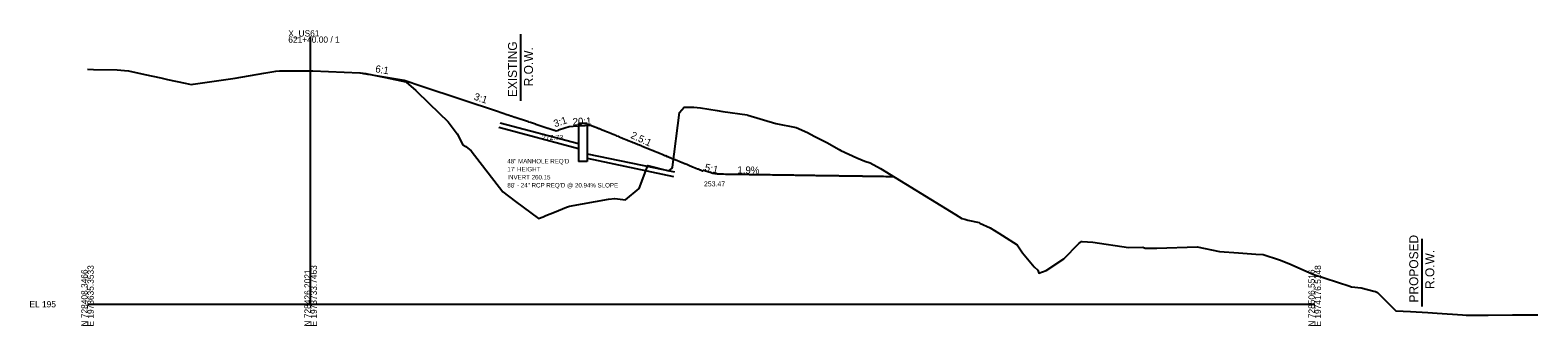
# Model space of a CAD drawing. Extents: x -26 to 1629, y -25 to 9635.
# Drawn here: x -26 to 650, y 3490 to 3623 of the extents above; entities that cross this region are included whole.
import ezdxf

# ---------------------------------------------------------------- set-up
doc = ezdxf.new("R2010")
doc.units = 0
for name, color, linetype in [('Default', 7, 'Continuous'), ('Draft_XS_Grid', 7, 'Continuous'), ('DTM CONTOURS_MAJOR', 7, 'Continuous'), ('DTM_X_GROUND', 7, 'Continuous'), ('XS_CELL', 7, 'Continuous'), ('XS_P_DRAINAGE', 7, 'Continuous'), ('XS_P_GROUND', 7, 'Continuous'), ('XS_P_ROW', 7, 'Continuous'), ('XS_P_TX_DCH', 7, 'Continuous'), ('XS_P_TX_FS_BS', 7, 'Continuous'), ('XS_X_ROW', 7, 'Continuous')]:
    doc.layers.add(name, color=color, linetype=linetype)

msp = doc.modelspace()

# ---------------------------------------------------------------- linework, layer by layer
at = {"layer": 'DTM_X_GROUND'}
msp.add_lwpolyline([(0, 3605.28), (2.68, 3605.23), (13.32, 3605.03), (16.59, 3604.73), (18.31, 3604.58), (25.67, 3602.96), (32.85, 3601.46), (35.86, 3600.73), (43.76, 3599.08), (46.43, 3598.52), (47.39, 3598.66), (66.25, 3601.39), (78.98, 3603.51), (84.39, 3604.52), (86.08, 3604.59), (87.2, 3604.64), (93.1, 3604.62), (101.01, 3604.6), (115.06, 3604.01), (122.06, 3603.72), (123.13, 3603.62), (124.81, 3603.45), (126.15, 3603.17), (133.54, 3601.57), (142.62, 3599.63), (142.78, 3599.48), (147.09, 3595.84), (153.2, 3589.92), (161.62, 3581.77), (165.72, 3576.42), (168.27, 3571.44), (169.57, 3570.66), (171.92, 3568.79), (186.1, 3550.37), (191.86, 3546.06), (202.11, 3538.39), (204.16, 3539.19), (205.48, 3539.73), (209.36, 3541.27), (214.72, 3543.43), (215.96, 3543.93), (233.43, 3547.02), (236.34, 3547.42), (241.16, 3546.78), (247.21, 3551.8), (251.1, 3562.23), (260.54, 3559.82), (262.02, 3560.94), (262.24, 3561.41), (265.31, 3585.98), (267.34, 3588.35), (271.68, 3588.3), (274.68, 3587.98), (282.22, 3586.78), (284.74, 3586.38), (295.61, 3584.84), (295.77, 3584.82), (295.99, 3584.78), (308.5, 3580.93), (317.6, 3579.19), (322.68, 3577.01), (325.6, 3575.26), (331.3, 3572.49), (336.92, 3569.29), (337.61, 3568.94), (344.82, 3565.68), (348.37, 3564.07), (350.75, 3563.31), (355.47, 3560.78), (388.99, 3540.26), (391.82, 3538.45), (393.22, 3538.06), (394.6, 3537.69), (399.58, 3536.65), (399.97, 3536.35), (404.54, 3534.23), (408.39, 3531.87), (408.43, 3531.85), (416.68, 3526.57), (419.11, 3523.07), (424.28, 3516.78), (425.92, 3515.28), (426.39, 3513.96), (429.6, 3515.18), (437.51, 3520.41), (444.3, 3527.23), (445.55, 3528.18), (445.73, 3528.17), (450.6, 3527.76), (466.49, 3525.39), (472.94, 3525.51), (473.98, 3525.19), (479.17, 3525.18), (497.34, 3525.7), (507.4, 3523.58), (515.77, 3523.1), (523.59, 3522.42), (526.92, 3522.33), (534.2, 3519.84), (537.69, 3518.58), (539.41, 3517.77), (549.19, 3513.43), (565.69, 3508.07), (566.08, 3507.92), (566.44, 3507.85), (570.83, 3507.3), (576.56, 3505.89), (577.22, 3505.75), (578.15, 3505.22), (586.3, 3497.08), (593, 3496.69), (600.64, 3496.25), (604.93, 3496), (616.16, 3495.24), (617.91, 3495.15), (627.74, 3495.13), (638.58, 3495.24), (650, 3495.24)], dxfattribs=at)
at = {"layer": 'XS_CELL'}
for p, q in [((100, 3500), (100, 3620)), ((0, 3500), (100, 3500)), ((100, 3500), (550, 3500))]:
    msp.add_line(p, q, dxfattribs=at)
at = {"layer": 'XS_P_DRAINAGE'}
for p, q in [((184.88, 3581.32), (220, 3571.97)), ((184.36, 3579.39), (220.11, 3569.87)), ((220, 3581.01), (220, 3563.98)), ((224, 3581.01), (220, 3581.01)), ((224, 3581.01), (224, 3563.98)), ((224, 3563.98), (220, 3563.98)), ((224, 3567.45), (263.02, 3559.28)), ((224, 3565.4), (262.61, 3557.32))]:
    msp.add_line(p, q, dxfattribs=at)
at = {"layer": 'XS_P_GROUND'}
for points in [[(122, 3603.73), (122.36, 3603.67), (123.4, 3603.49), (123.92, 3603.41), (125.48, 3603.15), (127.03, 3602.89), (127.55, 3602.8), (142, 3600.39)], [(142, 3600.39), (149.91, 3597.76), (150.24, 3597.64), (184.18, 3586.33), (184.89, 3586.1), (184.9, 3586.09), (185.34, 3585.94), (185.39, 3585.93), (187.15, 3585.34), (187.34, 3585.28), (187.45, 3585.24), (188.95, 3584.74), (189.77, 3584.47), (189.86, 3584.44), (191.55, 3583.87), (191.67, 3583.83), (193.42, 3583.25), (193.49, 3583.23), (194.38, 3582.93), (194.4, 3582.92), (194.45, 3582.91), (196.23, 3582.32), (196.25, 3582.31), (197.14, 3582.01), (197.16, 3582.01), (197.69, 3581.83), (197.71, 3581.82), (198.55, 3581.54), (198.56, 3581.54), (198.98, 3581.4), (199, 3581.39), (199.89, 3581.09), (199.92, 3581.09), (200.81, 3580.79), (200.87, 3580.77), (203.12, 3580.02), (203.13, 3580.02), (203.58, 3579.87), (203.62, 3579.85), (204, 3579.73), (204.51, 3579.55), (206.3, 3578.96), (206.38, 3578.93), (206.43, 3578.92), (208.26, 3578.31), (208.28, 3578.3), (209.2, 3577.99), (209.24, 3577.98), (210, 3577.73), (210, 3577.73), (211.08, 3578.08), (211.15, 3578.11), (213.91, 3579.03), (213.96, 3579.04), (215.8, 3579.66), (215.83, 3579.67), (216, 3579.73), (216.02, 3579.73), (217.7, 3579.81), (217.72, 3579.81), (225.73, 3580.21)], [(225.72, 3580.21), (225.83, 3580.17), (225.84, 3580.17), (226.96, 3579.71), (227.04, 3579.67), (228.1, 3579.24), (228.24, 3579.19), (229.23, 3578.78), (229.43, 3578.7), (230.36, 3578.32), (230.62, 3578.21), (231.5, 3577.85), (231.81, 3577.73), (232.63, 3577.39), (232.99, 3577.24), (233.76, 3576.93), (234.49, 3576.63), (234.9, 3576.46), (235.62, 3576.17), (236.03, 3576), (236.74, 3575.71), (237.16, 3575.54), (237.86, 3575.25), (238.3, 3575.07), (238.98, 3574.79), (239.43, 3574.61), (240.1, 3574.33), (240.56, 3574.15), (241.22, 3573.88), (241.7, 3573.68), (242.34, 3573.42), (242.83, 3573.22), (243.46, 3572.96), (243.96, 3572.76), (244.58, 3572.51), (245.1, 3572.29), (245.69, 3572.05), (246.23, 3571.83), (246.81, 3571.59), (247.36, 3571.37), (247.92, 3571.14), (248.5, 3570.9), (249.04, 3570.68), (249.63, 3570.44), (250.15, 3570.23), (250.76, 3569.98), (251.26, 3569.77), (251.9, 3569.51), (252.37, 3569.32), (253.03, 3569.05), (253.48, 3568.87), (254.16, 3568.59), (254.58, 3568.41), (255.3, 3568.12), (255.69, 3567.96), (256.43, 3567.66), (256.79, 3567.51), (257.56, 3567.2), (257.89, 3567.06), (258.7, 3566.73), (258.98, 3566.61), (259.83, 3566.27), (260.08, 3566.17), (260.96, 3565.81), (261.17, 3565.72), (262.1, 3565.34), (262.25, 3565.28), (263.23, 3564.88), (263.33, 3564.84), (264.36, 3564.42), (264.41, 3564.4), (265.23, 3564.06), (265.47, 3563.96), (265.5, 3563.95), (266.5, 3563.54), (266.63, 3563.49), (267.52, 3563.13), (267.76, 3563.03), (268.54, 3562.71), (268.9, 3562.56), (269.57, 3562.29), (270.03, 3562.1), (270.59, 3561.87), (271.16, 3561.64), (271.62, 3561.45), (272.3, 3561.17), (272.64, 3561.03), (273.43, 3560.71), (273.66, 3560.61), (274.56, 3560.25), (274.69, 3560.19), (275.7, 3559.78), (275.71, 3559.78), (275.86, 3559.72)], [(282.23, 3558.47), (281.49, 3558.51), (281.36, 3558.51), (280.73, 3558.54), (280.54, 3558.55), (280.45, 3558.58), (280.23, 3558.65), (279.8, 3558.79), (279.1, 3559.02), (278.42, 3559.25), (277.96, 3559.4), (277.04, 3559.7), (276.83, 3559.77), (276.68, 3559.82), (275.86, 3560.09)], [(361.45, 3557.12), (361.35, 3557.12), (361.34, 3557.12), (360.19, 3557.14), (360.16, 3557.14), (359.03, 3557.15), (358.98, 3557.15), (357.87, 3557.17), (357.8, 3557.17), (356.72, 3557.19), (356.61, 3557.19), (355.56, 3557.2), (355.43, 3557.21), (354.4, 3557.22), (354.25, 3557.22), (353.24, 3557.24), (353.07, 3557.24), (352.09, 3557.25), (351.89, 3557.26), (350.93, 3557.27), (350.71, 3557.27), (349.77, 3557.29), (349.54, 3557.29), (348.61, 3557.3), (348.36, 3557.31), (347.46, 3557.32), (347.18, 3557.33), (346.3, 3557.34), (346, 3557.34), (345.14, 3557.35), (344.83, 3557.36), (343.98, 3557.37), (343.66, 3557.38), (342.83, 3557.39), (342.48, 3557.39), (341.67, 3557.4), (341.31, 3557.41), (340.51, 3557.42), (340.13, 3557.43), (339.35, 3557.44), (338.96, 3557.44), (338.19, 3557.46), (337.78, 3557.46), (337.04, 3557.47), (336.6, 3557.48), (335.88, 3557.49), (335.43, 3557.5), (334.72, 3557.51), (334.25, 3557.51), (333.56, 3557.52), (333.07, 3557.53), (332.41, 3557.54), (331.9, 3557.55), (331.25, 3557.56), (330.72, 3557.56), (330.09, 3557.57), (329.54, 3557.58), (328.93, 3557.59), (328.36, 3557.6), (327.78, 3557.61), (327.18, 3557.61), (326.62, 3557.62), (326, 3557.63), (325.46, 3557.64), (324.83, 3557.65), (324.3, 3557.66), (323.65, 3557.67), (323.15, 3557.67), (322.47, 3557.68), (321.99, 3557.69), (321.29, 3557.7), (320.83, 3557.71), (320.11, 3557.72), (319.67, 3557.72), (318.94, 3557.73), (318.52, 3557.74), (317.76, 3557.75), (317.36, 3557.76), (316.58, 3557.77), (316.2, 3557.77), (315.4, 3557.78), (315.04, 3557.79), (314.23, 3557.8), (313.89, 3557.81), (313.05, 3557.82), (312.73, 3557.82), (311.87, 3557.84), (311.57, 3557.84), (310.7, 3557.85), (310.41, 3557.86), (309.52, 3557.87), (309.25, 3557.87), (308.34, 3557.89), (308.1, 3557.89), (307.17, 3557.9), (306.94, 3557.91), (305.99, 3557.92), (305.78, 3557.92), (304.81, 3557.94), (304.62, 3557.94), (303.64, 3557.96), (303.47, 3557.96), (302.46, 3557.97), (302.31, 3557.97), (301.29, 3557.99), (301.15, 3557.99), (300.11, 3558.01), (299.99, 3558.01), (298.93, 3558.02), (298.84, 3558.02), (297.76, 3558.04), (297.68, 3558.04), (296.58, 3558.06), (296.52, 3558.06), (295.41, 3558.07), (295.36, 3558.07), (294.23, 3558.09), (294.21, 3558.09), (293.06, 3558.11), (293.05, 3558.11), (292.52, 3558.12), (291.89, 3558.13), (291.81, 3558.13), (290.73, 3558.14), (290.5, 3558.15), (289.58, 3558.16), (289.19, 3558.16), (288.42, 3558.18), (288.17, 3558.18), (287.84, 3558.18), (287.48, 3558.18), (287.03, 3558.15), (286.33, 3558.18), (285.9, 3558.19), (285.07, 3558.22), (284.76, 3558.23), (283.8, 3558.26), (283.63, 3558.26), (282.53, 3558.3), (282.5, 3558.3), (282.23, 3558.31)]]:
    msp.add_lwpolyline(points, dxfattribs=at)
at = {"layer": 'XS_P_ROW'}
msp.add_line((598, 3529.3), (598, 3498.98), dxfattribs=at)
at = {"layer": 'XS_X_ROW'}
msp.add_line((194, 3621.1), (194, 3591.2), dxfattribs=at)

# ---------------------------------------------------------------- texts
at = {"layer": 'Default'}
for p in [(141.96, 3600.33), (282.19, 3558.41)]:
    msp.add_text('X', height=0.12, dxfattribs=at).set_placement(p)
at = {"layer": 'Draft_XS_Grid'}
msp.add_text('-', height=0.0001, dxfattribs=at).set_placement((0, 3500))
at = {"layer": 'DTM CONTOURS_MAJOR'}
for p in [(121.96, 3603.67), (141.96, 3600.33), (203.96, 3579.67), (209.96, 3577.67), (215.96, 3579.67), (229.96, 3580.37), (265.19, 3565.51), (275.82, 3560.03), (275.82, 3560.03), (292.48, 3559.98)]:
    msp.add_text('X', height=0.12, dxfattribs=at).set_placement(p)
at = {"layer": 'XS_CELL'}
for s, p in [('X_US61', (90, 3620)), ('621+40.00 / 1', (90, 3617.2)), ('EL 195', (-26, 3498.6))]:
    msp.add_text(s, height=2.8, dxfattribs=at).set_placement(p)
for s, p in [('N 728408.3466', (0, 3490)), ('E 1973635.3533', (2.8, 3490)), ('N 728426.2021', (100, 3490)), ('E 1973733.7463', (102.8, 3490)), ('N 728506.5516', (550, 3490)), ('E 1974176.5148', (552.8, 3490))]:
    msp.add_text(s, height=2.8, rotation=90, dxfattribs=at).set_placement(p)
at = {"layer": 'XS_P_DRAINAGE'}
for s, p in [('48" MANHOLE REQ\'D', (188.16, 3563.12)), ("17' HEIGHT", (188.16, 3559.52)), ('88\' - 24" RCP REQ\'D @ 20.94% SLOPE', (188.16, 3552.32)), ('INVERT 260.15', (188.16, 3555.92))]:
    msp.add_text(s, height=2, dxfattribs=at).set_placement(p)
at = {"layer": 'XS_P_ROW'}
for s, p in [('PROPOSED', (596.37, 3500.77)), ('R.O.W.', (603.57, 3506.84))]:
    msp.add_text(s, height=4, rotation=90, dxfattribs=at).set_placement(p)
at = {"layer": 'XS_P_TX_DCH'}
for s, p in [('272.73', (203.66, 3573.62)), ('253.47', (276.29, 3552.83))]:
    msp.add_text(s, height=2.25, dxfattribs=at).set_placement(p)
at = {"layer": 'XS_P_TX_FS_BS'}
for s, rotation, p in [('6:1', 350.53766, (128.82, 3604.02)), ('3:1', 341.56507, (172.91, 3591.75)), ('3:1', 18.43493, (209.5, 3579.29)), ('20:1', 2.86241, (217.5, 3580.16)), ('2.5:1', 335.08561, (243.14, 3574.65)), ('5:1', 347.56043, (276.42, 3559.9)), ('1.9%', 358.91971, (291.24, 3558.6))]:
    msp.add_text(s, height=3.24, rotation=rotation, dxfattribs=at).set_placement(p)
at = {"layer": 'XS_X_ROW'}
for s, p in [('EXISTING', (192.46, 3592.82)), ('R.O.W.', (199.66, 3597.67))]:
    msp.add_text(s, height=4, rotation=90, dxfattribs=at).set_placement(p)

doc.saveas('drawing.dxf')
